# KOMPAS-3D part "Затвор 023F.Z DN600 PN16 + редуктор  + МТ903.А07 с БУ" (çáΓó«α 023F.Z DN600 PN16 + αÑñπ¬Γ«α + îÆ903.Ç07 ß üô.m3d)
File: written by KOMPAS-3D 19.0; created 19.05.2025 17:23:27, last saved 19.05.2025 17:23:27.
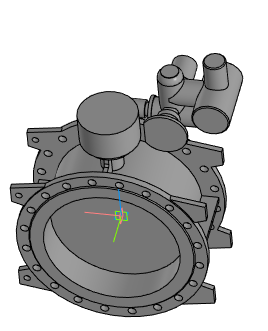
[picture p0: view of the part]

Document properties: Полное имя файла: Затвор 023F.Z DN600 PN16 + редуктор + МТ903.А07 с БУ.a3d

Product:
- Part/product: Затвор 023F.Z DN600 PN16 + редуктор  + МТ903.А07 с БУ
    Масса: 592.685

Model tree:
1. Операция без истории:1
